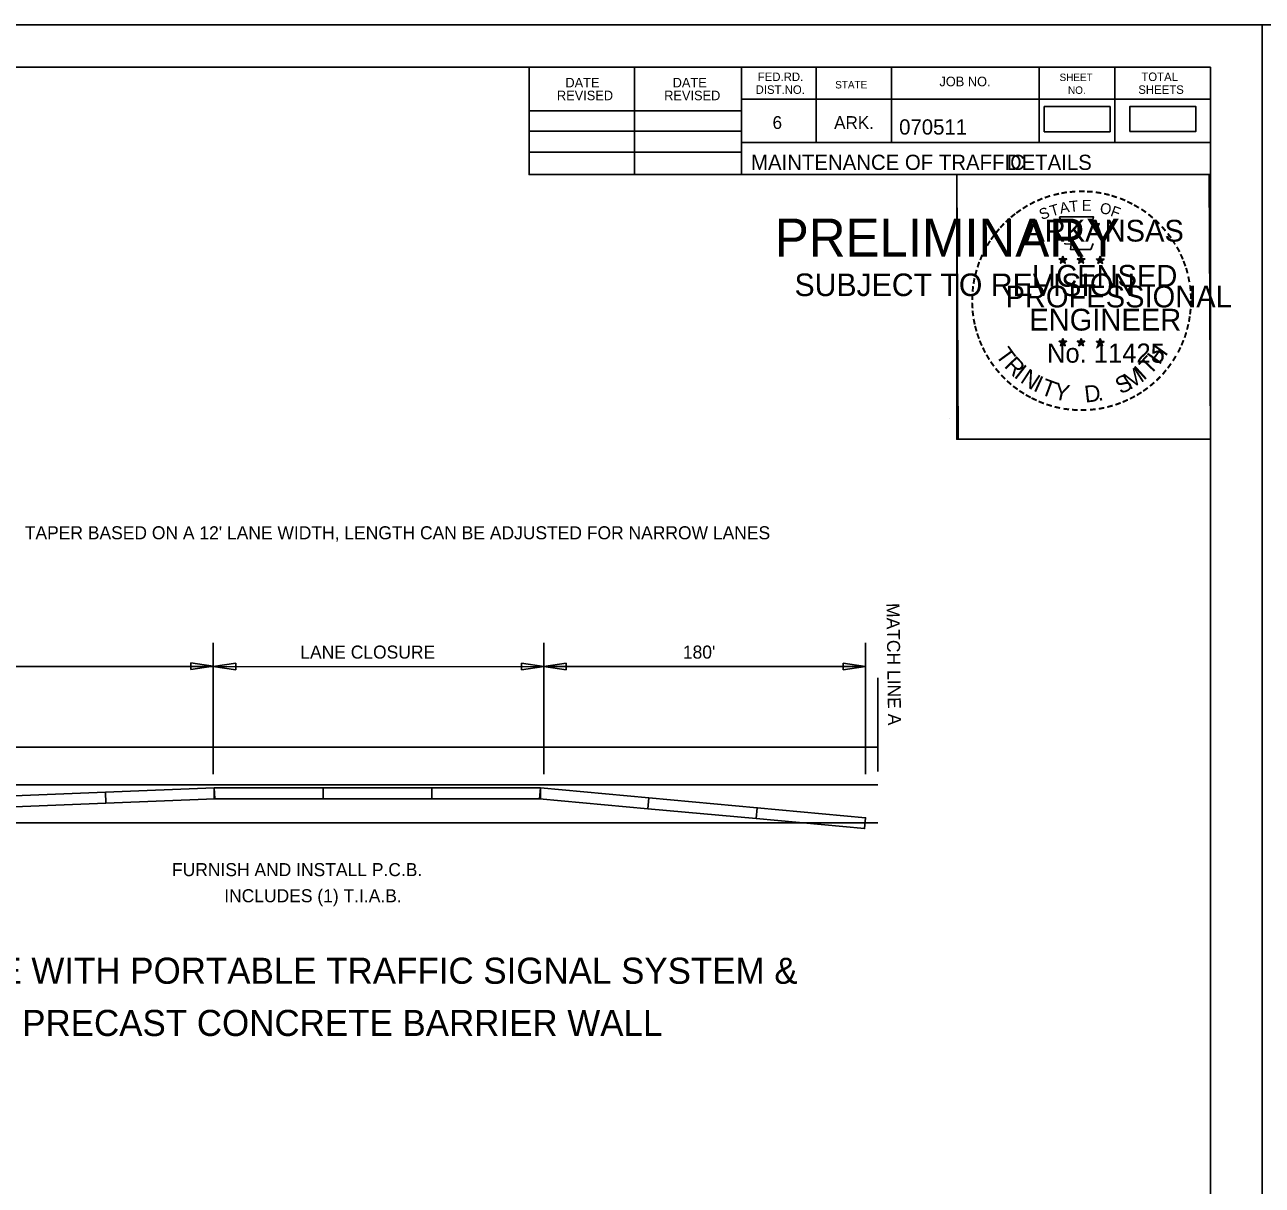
# Model space of a CAD drawing. Extents: x 1398460 to 1408037, y 380768 to 383968.
# Drawn here: x 1400097 to 1400666, y 382368 to 382901 of the extents above; entities that cross this region are included whole.
import ezdxf

# ---------------------------------------------------------------- set-up
doc = ezdxf.new("R2010")
doc.units = 0
for name, color, linetype in [('Default', 7, 'Continuous'), ('R_Border', 7, 'Continuous'), ('R_Border PE', 7, 'Continuous'), ('R_Border Prem', 7, 'Continuous'), ('R_Dimension', 7, 'Continuous'), ('R_No Plot', 7, 'Continuous'), ('T_Vehicle Path Rt', 7, 'Continuous')]:
    doc.layers.add(name, color=color, linetype=linetype)

msp = doc.modelspace()

# ---------------------------------------------------------------- linework, layer by layer
at = {"layer": 'Default'}
for p, q in [((1400183.41, 382616.76), (1400183.41, 382556.41)), ((1400335.34, 382616.76), (1400335.34, 382556.41)), ((1400483.24, 382616.76), (1400483.24, 382556.41)), ((1400173.1, 382604.56), (1400173.1, 382607.65)), ((1400173.1, 382607.65), (1400183.41, 382606.11)), ((1400183.41, 382605.97), (1400193.71, 382607.52)), ((1400193.71, 382607.52), (1400193.71, 382604.43)), ((1400325.04, 382604.43), (1400325.04, 382607.52)), ((1400325.04, 382607.52), (1400335.34, 382605.97)), ((1400335.34, 382605.97), (1400345.65, 382607.52)), ((1400345.65, 382607.52), (1400345.65, 382604.43)), ((1400472.93, 382604.43), (1400472.93, 382607.52)), ((1400472.93, 382607.52), (1400483.24, 382605.97)), ((1400183.41, 382605.97), (1399933.68, 382605.97)), ((1400183.41, 382606.11), (1400173.1, 382604.56)), ((1400193.71, 382604.43), (1400183.41, 382605.97)), ((1400335.34, 382605.84), (1400183.41, 382605.97)), ((1400335.34, 382605.97), (1400325.04, 382604.43)), ((1400335.34, 382605.97), (1400483.24, 382605.97)), ((1400345.65, 382604.43), (1400335.34, 382605.97)), ((1400483.24, 382605.97), (1400472.93, 382604.43)), ((1400488.87, 382600.78), (1400488.87, 382557.73)), ((1399825.51, 382568.89), (1400488.87, 382568.89)), ((1399825.51, 382551.51), (1400488.87, 382551.51)), ((1399825.51, 382534.12), (1400488.87, 382534.12))]:
    msp.add_line(p, q, dxfattribs=at)
at = {"layer": 'R_Border'}
for p, q in [((1399060.87, 382881.42), (1400641.77, 382881.42)), ((1400328.57, 382832.02), (1400328.57, 382881.42)), ((1400376.97, 382832.02), (1400376.97, 382881.42)), ((1400426.27, 382881.42), (1400426.27, 382832.02)), ((1400460.47, 382881.42), (1400460.47, 382846.72)), ((1400495.17, 382881.42), (1400495.17, 382846.72)), ((1400563.07, 382881.42), (1400563.07, 382846.72)), ((1400597.77, 382881.42), (1400597.77, 382846.72)), ((1400641.77, 381854.12), (1400641.77, 382881.42)), ((1400641.77, 382866.72), (1400426.27, 382866.72)), ((1400641.77, 382866.82), (1400641.77, 382866.82)), ((1400328.57, 382861.32), (1400426.27, 382861.32)), ((1400328.57, 382852.02), (1400426.27, 382852.02)), ((1400641.77, 382846.72), (1400426.27, 382846.72)), ((1400441.07, 382846.72), (1400641.77, 382846.72)), ((1400328.57, 382842.32), (1400426.27, 382842.32)), ((1400641.77, 382832.02), (1400328.57, 382832.02))]:
    msp.add_line(p, q, dxfattribs=at)
at = {"layer": 'R_Border PE'}
for p, q in [((1400573.94, 382794.56), (1400573.73, 382793.3)), ((1400573.94, 382792.74), (1400573.94, 382794.56)), ((1400573.94, 382794.56), (1400574.18, 382793.31)), ((1400582.29, 382794.56), (1400582.08, 382793.3)), ((1400582.29, 382792.74), (1400582.29, 382794.56)), ((1400582.29, 382794.56), (1400582.53, 382793.31)), ((1400572.19, 382793.29), (1400573.94, 382792.74)), ((1400572.19, 382793.29), (1400573.46, 382793.07)), ((1400572.19, 382793.29), (1400573.38, 382792.68)), ((1400572.86, 382791.25), (1400573.94, 382792.74)), ((1400572.86, 382791.25), (1400573.49, 382792.47)), ((1400572.86, 382791.25), (1400573.93, 382792.34)), ((1400575, 382791.25), (1400573.93, 382792.32)), ((1400575.67, 382793.29), (1400573.94, 382792.74)), ((1400575, 382791.25), (1400573.94, 382792.74)), ((1400575.67, 382793.29), (1400574.24, 382793.05)), ((1400575, 382791.25), (1400574.32, 382792.71)), ((1400575.67, 382793.29), (1400574.65, 382792.78)), ((1400580.54, 382793.29), (1400582.29, 382792.74)), ((1400580.54, 382793.29), (1400581.81, 382793.07)), ((1400580.54, 382793.29), (1400581.73, 382792.68)), ((1400581.21, 382791.25), (1400582.29, 382792.74)), ((1400581.21, 382791.25), (1400581.84, 382792.47)), ((1400581.21, 382791.25), (1400582.28, 382792.34)), ((1400583.35, 382791.25), (1400582.28, 382792.32)), ((1400584.02, 382793.29), (1400582.29, 382792.74)), ((1400583.35, 382791.25), (1400582.29, 382792.74)), ((1400584.02, 382793.29), (1400582.59, 382793.05)), ((1400583.35, 382791.25), (1400582.67, 382792.71)), ((1400584.02, 382793.29), (1400583, 382792.78)), ((1400589.36, 382793.23), (1400591.11, 382792.68)), ((1400589.36, 382793.23), (1400590.63, 382793.01)), ((1400589.36, 382793.23), (1400590.55, 382792.62)), ((1400590.03, 382791.19), (1400591.11, 382792.68)), ((1400590.03, 382791.19), (1400590.66, 382792.41)), ((1400590.03, 382791.19), (1400591.1, 382792.28)), ((1400591.11, 382794.5), (1400590.9, 382793.24)), ((1400592.17, 382791.19), (1400591.1, 382792.26)), ((1400591.11, 382792.68), (1400591.11, 382794.5)), ((1400591.11, 382794.5), (1400591.35, 382793.25)), ((1400592.84, 382793.23), (1400591.11, 382792.68)), ((1400592.17, 382791.19), (1400591.11, 382792.68)), ((1400592.84, 382793.23), (1400591.41, 382792.99)), ((1400592.17, 382791.19), (1400591.49, 382792.65)), ((1400592.84, 382793.23), (1400591.82, 382792.72)), ((1400572.17, 382755.43), (1400573.92, 382754.87)), ((1400572.17, 382755.43), (1400573.44, 382755.2)), ((1400572.17, 382755.43), (1400573.36, 382754.82)), ((1400572.84, 382753.39), (1400573.92, 382754.87)), ((1400573.92, 382756.7), (1400573.71, 382755.44)), ((1400573.92, 382754.87), (1400573.92, 382756.7)), ((1400573.92, 382756.7), (1400574.16, 382755.45)), ((1400575.65, 382755.43), (1400573.92, 382754.87)), ((1400574.98, 382753.39), (1400573.92, 382754.87)), ((1400575.65, 382755.43), (1400574.22, 382755.18)), ((1400574.98, 382753.39), (1400574.3, 382754.84)), ((1400575.65, 382755.43), (1400574.63, 382754.92)), ((1400580.52, 382755.43), (1400582.26, 382754.87)), ((1400580.52, 382755.43), (1400581.78, 382755.2)), ((1400580.52, 382755.43), (1400581.7, 382754.82)), ((1400581.18, 382753.39), (1400582.26, 382754.87)), ((1400582.26, 382756.7), (1400582.06, 382755.44)), ((1400582.26, 382754.87), (1400582.26, 382756.7)), ((1400582.26, 382756.7), (1400582.51, 382755.45)), ((1400584, 382755.43), (1400582.26, 382754.87)), ((1400583.33, 382753.39), (1400582.26, 382754.87)), ((1400584, 382755.43), (1400582.57, 382755.18)), ((1400583.33, 382753.39), (1400582.64, 382754.84)), ((1400584, 382755.43), (1400582.98, 382754.92)), ((1400589.35, 382755.38), (1400591.1, 382754.82)), ((1400589.35, 382755.38), (1400590.62, 382755.15)), ((1400589.35, 382755.38), (1400590.54, 382754.77)), ((1400590.02, 382753.34), (1400591.1, 382754.82)), ((1400591.1, 382756.65), (1400590.89, 382755.39)), ((1400591.1, 382754.82), (1400591.1, 382756.65)), ((1400591.1, 382756.65), (1400591.34, 382755.4)), ((1400592.83, 382755.38), (1400591.1, 382754.82)), ((1400592.16, 382753.34), (1400591.1, 382754.82)), ((1400592.83, 382755.38), (1400591.4, 382755.13)), ((1400592.16, 382753.34), (1400591.48, 382754.79)), ((1400592.83, 382755.38), (1400591.81, 382754.87)), ((1400572.84, 382753.39), (1400573.47, 382754.61)), ((1400572.84, 382753.39), (1400573.91, 382754.47)), ((1400574.98, 382753.39), (1400573.91, 382754.46)), ((1400581.18, 382753.39), (1400581.81, 382754.61)), ((1400581.18, 382753.39), (1400582.25, 382754.47)), ((1400583.33, 382753.39), (1400582.25, 382754.46)), ((1400590.02, 382753.34), (1400590.65, 382754.56)), ((1400590.02, 382753.34), (1400591.09, 382754.42)), ((1400592.16, 382753.34), (1400591.09, 382754.41))]:
    msp.add_line(p, q, dxfattribs=at)
for points in [[(1400572.4, 382812.68), (1400573.74, 382808.55)], [(1400589.95, 382808.07), (1400590.66, 382809.49), (1400587.24, 382809.37), (1400587.98, 382812.68), (1400572.4, 382812.68)], [(1400574.86, 382800.57), (1400574.86, 382800.13), (1400577.67, 382800.04), (1400577.4, 382797.67), (1400586.75, 382797.67), (1400587.76, 382800.35)], [(1400573.94, 382794.56), (1400575, 382791.25), (1400572.19, 382793.29), (1400575.67, 382793.29), (1400572.86, 382791.25), (1400573.94, 382794.56)], [(1400582.29, 382794.56), (1400583.35, 382791.25), (1400580.54, 382793.29), (1400584.02, 382793.29), (1400581.21, 382791.25), (1400582.29, 382794.56)], [(1400591.11, 382794.5), (1400592.17, 382791.19), (1400589.36, 382793.23), (1400592.84, 382793.23), (1400590.03, 382791.19), (1400591.11, 382794.5)], [(1400573.92, 382756.7), (1400574.98, 382753.39), (1400572.17, 382755.43), (1400575.65, 382755.43), (1400572.84, 382753.39), (1400573.92, 382756.7)], [(1400582.26, 382756.7), (1400583.33, 382753.39), (1400580.52, 382755.43), (1400584, 382755.43), (1400581.18, 382753.39), (1400582.26, 382756.7)], [(1400591.1, 382756.65), (1400592.16, 382753.34), (1400589.35, 382755.38), (1400592.83, 382755.38), (1400590.02, 382753.34), (1400591.1, 382756.65)]]:
    msp.add_lwpolyline(points, dxfattribs=at)
for centre, radius in [((1400573.93, 382792.73), 0.861), ((1400573.93, 382792.73), 0.723), ((1400573.93, 382792.73), 0.579), ((1400573.93, 382792.73), 0.495), ((1400573.93, 382792.73), 0.374), ((1400573.93, 382792.73), 0.248), ((1400573.93, 382792.73), 0.148), ((1400582.28, 382792.73), 0.861), ((1400582.28, 382792.73), 0.723), ((1400582.28, 382792.73), 0.579), ((1400582.28, 382792.73), 0.495), ((1400582.28, 382792.73), 0.374), ((1400582.28, 382792.73), 0.248), ((1400582.28, 382792.73), 0.148), ((1400591.1, 382792.67), 0.861), ((1400591.1, 382792.67), 0.723), ((1400591.1, 382792.67), 0.579), ((1400591.1, 382792.67), 0.495), ((1400591.1, 382792.67), 0.374), ((1400591.1, 382792.67), 0.248), ((1400591.1, 382792.67), 0.148), ((1400573.91, 382754.87), 0.861), ((1400573.91, 382754.87), 0.723), ((1400573.91, 382754.87), 0.579), ((1400573.91, 382754.87), 0.495), ((1400573.91, 382754.87), 0.374), ((1400573.91, 382754.87), 0.248), ((1400573.91, 382754.87), 0.148), ((1400582.26, 382754.87), 0.861), ((1400582.26, 382754.87), 0.723), ((1400582.26, 382754.87), 0.579), ((1400582.26, 382754.87), 0.495), ((1400582.26, 382754.87), 0.374), ((1400582.26, 382754.87), 0.248), ((1400582.26, 382754.87), 0.148), ((1400591.09, 382754.82), 0.861), ((1400591.09, 382754.82), 0.723), ((1400591.09, 382754.82), 0.579), ((1400591.09, 382754.82), 0.495), ((1400591.09, 382754.82), 0.374), ((1400591.09, 382754.82), 0.248), ((1400591.09, 382754.82), 0.148)]:
    msp.add_circle(centre, radius, dxfattribs=at)
at = {"layer": 'R_Dimension'}
for points in [[(1400565.37, 382851.73), (1400595.64, 382851.73), (1400595.64, 382863.28), (1400565.37, 382863.28)], [(1400604.7, 382851.79), (1400634.97, 382851.79), (1400634.97, 382863.35), (1400604.7, 382863.35)]]:
    msp.add_lwpolyline(points, close=True, dxfattribs=at)
at = {"layer": 'R_No Plot'}
for p, q in [((1398998.86, 382900.89), (1400665.53, 382900.89)), ((1400521.94, 382719.74), (1400521.94, 382719.74))]:
    msp.add_line(p, q, dxfattribs=at)
for points in [[(1398998.83, 382900.89), (1400665.53, 382900.89), (1400665.53, 381834.2), (1398998.83, 381834.2)], [(1400665.53, 382900.89), (1402332.23, 382900.89), (1402332.23, 381834.2), (1400665.53, 381834.2)], [(1400230.47, 382881.42), (1400328.57, 382881.42), (1400328.57, 382832.02), (1400409.13, 382832.02), (1400525.12, 382832.02), (1400525.12, 382710.36), (1400641.77, 382710.36), (1400641.77, 381854.12), (1399060.87, 381854.12), (1399060.87, 382881.42)], [(1400525.12, 382832.02), (1400641.16, 382832.02), (1400641.77, 382710.36), (1400525.73, 382710.36)]]:
    msp.add_lwpolyline(points, close=True, dxfattribs=at)
at = {"layer": 'T_Vehicle Path Rt'}
for points in [[(1400133.9, 382548.17), (1400183.86, 382550.14), (1400184.06, 382545.15), (1400134.1, 382543.17)], [(1400183.86, 382550.14), (1400233.86, 382550.14), (1400233.86, 382545.14), (1400183.86, 382545.14)], [(1400233.86, 382550.14), (1400283.86, 382550.14), (1400283.86, 382545.14), (1400233.86, 382545.14)], [(1400283.86, 382550.14), (1400333.86, 382550.14), (1400333.86, 382545.14), (1400283.86, 382545.14)], [(1400333.86, 382550.14), (1400383.65, 382545.58), (1400383.2, 382540.6), (1400333.41, 382545.16)], [(1400083.94, 382546.2), (1400133.9, 382548.17), (1400134.1, 382543.17), (1400084.14, 382541.2)], [(1400383.65, 382545.58), (1400433.45, 382541.02), (1400432.99, 382536.04), (1400383.2, 382540.6)], [(1400433.45, 382541.02), (1400483.24, 382536.45), (1400482.78, 382531.48), (1400432.99, 382536.04)]]:
    msp.add_lwpolyline(points, close=True, dxfattribs=at)

# ---------------------------------------------------------------- texts
at = {"layer": 'Default'}
msp.add_text('MATCH LINE A', height=6, rotation=270.8059, dxfattribs=at).set_placement((1400492.8, 382635.07))
for s, height, p in [('LANE CLOSURE', 6, (1400223.42, 382609.58)), ("180'", 6, (1400399.25, 382609.58)), ('FURNISH AND INSTALL P.C.B. ', 6, (1400164.45, 382509.6)), ('INCLUDES (1) T.I.A.B.', 6, (1400188.45, 382497.6)), ('LANE CLOSURE WITH PORTABLE TRAFFIC SIGNAL SYSTEM &', 12, (1399971.4, 382460.14)), ('PRECAST CONCRETE BARRIER WALL', 12, (1400095.6, 382436.14))]:
    msp.add_text(s, height=height, dxfattribs=at).set_placement(p)
at = {"layer": 'R_Border'}
for s, height, p in [('DATE', 4.396, (1400345.26, 382872.1)), ('DATE', 4.396, (1400394.56, 382872.1)), ('FED.RD.', 3.91, (1400433.67, 382875.02)), ('STATE', 3.42, (1400469.27, 382871.62)), ('JOB NO.', 4.396, (1400517.17, 382872.62)), ('SHEET', 3.42, (1400572.37, 382875.02)), ('TOTAL', 3.91, (1400609.97, 382875.02)), ('REVISED', 4.396, (1400341.36, 382866.2)), ('REVISED', 4.396, (1400390.66, 382866.2)), ('DIST.NO.', 3.91, (1400432.67, 382869.12)), ('NO.', 3.42, (1400576.27, 382869.12)), ('SHEETS', 3.91, (1400608.57, 382869.12)), ('6', 5.86, (1400440.47, 382853.02)), ('ARK.', 5.861, (1400468.77, 382853.02)), ('070511', 7, (1400498.65, 382850.42)), ('MAINTENANCE OF TRAFFIC', 7, (1400430.58, 382834.17)), (' DETAILS', 7, (1400545.58, 382834.17))]:
    msp.add_text(s, height=height, dxfattribs=at).set_placement(p)
at = {"layer": 'R_Border PE'}
for s, height, rotation, p in [('-', 8, 13.6302, (1400569.89, 382819.52)), ('-', 8, 10.2193, (1400573.28, 382820.33)), ('-', 8, 5.8968, (1400576.92, 382820.88)), ('-', 8, 0.1862, (1400580.78, 382821.24)), ('-', 8, 357.743, (1400584.4, 382821.18)), ('-', 8, 352.1617, (1400588.12, 382820.9)), ('-', 8, 347.2049, (1400591.71, 382820.33)), ('-', 8, 34.0636, (1400556.82, 382813.54)), ('-', 8, 28.7918, (1400559.8, 382815.39)), ('-', 8, 24.3072, (1400562.97, 382816.97)), ('-', 8, 19.1761, (1400566.14, 382818.32)), ('T', 5, 16.4036, (1400568.74, 382812.73)), ('A', 5, 11.2132, (1400572.87, 382813.98)), ('T', 5, 6.0228, (1400577.12, 382814.81)), ('E', 5, 0.8323, (1400582.64, 382815.36)), ('O', 5, 350.4515, (1400590.66, 382814.31)), ('F', 5, 340.0707, (1400595.43, 382813.17)), ('-', 8, 342.3362, (1400594.89, 382819.55)), ('-', 8, 337.8551, (1400598.56, 382818.44)), ('-', 8, 334.1211, (1400601.72, 382817.08)), ('-', 8, 329.6409, (1400604.61, 382815.67)), ('-', 8, 42.9622, (1400549.38, 382807.59)), ('-', 8, 38.9507, (1400551.55, 382809.67)), ('-', 8, 36.2317, (1400553.93, 382811.56)), ('S', 5, 21.594, (1400564.17, 382811.07)), ('-', 8, 325.8627, (1400607.83, 382813.86)), ('-', 8, 320.5297, (1400610.88, 382811.73)), ('-', 8, 50.6142, (1400545.13, 382802.77)), ('-', 8, 48.4231, (1400547.14, 382805.2)), ('-', 8, 315.5786, (1400613.87, 382809.29)), ('-', 8, 309.8797, (1400616.72, 382806.54)), ('-', 8, 58.0706, (1400541.44, 382797.3)), ('-', 8, 54.2325, (1400543.06, 382799.93)), ('-', 8, 306.6522, (1400619.34, 382803.53)), ('-', 7, 303.6753, (1400621.77, 382800.69)), ('-', 8, 67.7743, (1400538.58, 382791.17)), ('-', 8, 62.8713, (1400539.87, 382794.23)), ('-', 8, 299.6684, (1400623.37, 382797.66)), ('-', 8, 294.6628, (1400624.99, 382794.6)), ('-', 8, 72.3945, (1400537.48, 382788.02)), ('-', 8, 290.5728, (1400626.27, 382791.71)), ('-', 8, 285.1233, (1400627.44, 382788.81)), ('-', 8, 81.2013, (1400535.84, 382780.89)), ('-', 8, 75.461, (1400536.5, 382784.45)), ('-', 8, 280.5493, (1400628.44, 382785.1)), ('-', 8, 85.1863, (1400535.46, 382777.43)), ('-', 8, 276.5962, (1400629.25, 382781.26)), ('-', 8, 94.1959, (1400535.51, 382770.3)), ('-', 8, 89.0622, (1400535.33, 382773.93)), ('-', 8, 274.3301, (1400629.55, 382777.65)), ('-', 8, 269.9407, (1400629.72, 382774.49)), ('-', 8, 98.9479, (1400535.87, 382766.97)), ('-', 8, 260.9953, (1400629.27, 382767.89)), ('-', 8, 263.5172, (1400629.63, 382771.16)), ('-', 8, 101.7149, (1400536.54, 382763.3)), ('-', 8, 105.4578, (1400537.35, 382760.33)), ('-', 8, 255.7626, (1400628.72, 382764.5)), ('-', 8, 109.0874, (1400538.43, 382757.17)), ('-', 8, 114.0643, (1400539.7, 382754.19)), ('-', 8, 247.8887, (1400626.7, 382757.54)), ('-', 8, 252.8681, (1400627.82, 382760.9)), ('-', 8, 115.7289, (1400541.22, 382751.1)), ('-', 8, 120.4471, (1400543.01, 382748.17)), ('T', 7.7, 306.0406, (1400542.71, 382749.06)), ('T', 7.7, 46.6444, (1400613.87, 382739.53)), ('H', 7.7, 54.6088, (1400618.31, 382744.24)), ('-', 8, 244.6197, (1400625.39, 382754.39)), ('-', 8, 125.8934, (1400545.02, 382745.37)), ('R', 7.7, 314.005, (1400546.53, 382743.83)), ('I', 7.7, 321.9694, (1400551.03, 382739.17)), ('M', 7.7, 32.6563, (1400604.64, 382732.9)), ('I', 7.7, 42.1136, (1400611.06, 382737.14)), ('-', 8, 233.8452, (1400621.41, 382747.37)), ('-', 8, 239.0712, (1400623.42, 382750.63)), ('-', 8, 130.7181, (1400547.33, 382742.61)), ('-', 8, 134.2238, (1400549.92, 382739.88)), ('N', 7.7, 326.5002, (1400553.86, 382736.81)), ('I', 7.7, 335.3603, (1400559.91, 382732.88)), ('T', 7.7, 339.8912, (1400563.21, 382731.24)), ('S', 7.7, 26.9312, (1400600.44, 382730.87)), ('-', 8, 225.7653, (1400616.87, 382741.72)), ('-', 8, 231.2538, (1400619.26, 382744.54)), ('-', 8, 138.9338, (1400552.54, 382737.56)), ('-', 8, 144.6463, (1400555.32, 382735.53)), ('-', 8, 148.0898, (1400558.13, 382733.68)), ('Y', 7.7, 347.8556, (1400569.3, 382729.01)), ('D', 7.7, 6.3969, (1400584.22, 382727.22)), ('-', 8, 212.2491, (1400608.84, 382734.88)), ('-', 8, 215.7363, (1400611.51, 382736.81)), ('-', 8, 221.0851, (1400614.26, 382739.17)), ('-', 8, 151.5704, (1400561.02, 382732.05)), ('-', 8, 154.6002, (1400563.63, 382730.82)), ('-', 8, 158.5612, (1400566.75, 382729.55)), ('-', 8, 162.7983, (1400570.19, 382728.48)), ('.', 7.7, 13.7642, (1400590.18, 382727.86)), ('-', 8, 195.4743, (1400596.45, 382728.98)), ('-', 8, 200.7184, (1400599.84, 382730.19)), ('-', 8, 204.2516, (1400602.93, 382731.55)), ('-', 8, 207.3568, (1400606.05, 382733.15)), ('-', 8, 167.5555, (1400573.76, 382727.66)), ('-', 8, 173.1155, (1400577.62, 382727.11)), ('-', 8, 176.5183, (1400581.36, 382726.85)), ('-', 8, 181.5918, (1400585.08, 382726.94)), ('-', 8, 185.8167, (1400589.13, 382727.32)), ('-', 8, 191.2858, (1400592.81, 382727.98))]:
    msp.add_text(s, height=height, rotation=rotation, dxfattribs=at).set_placement(p)
for s, height, p in [('ARKANSAS', 10, (1400556.66, 382801.24)), ('LICENSED', 10, (1400559.65, 382780.5)), ('DWB', 0.05, (1400573.87, 382792.71)), ('DWB', 0.05, (1400582.22, 382792.71)), ('DWB', 0.05, (1400591.04, 382792.66)), ('PROFESSIONAL', 10, (1400547.53, 382770.98)), ('ENGINEER', 10, (1400558.47, 382760.35)), ('DWB', 0.05, (1400573.85, 382754.85)), ('DWB', 0.05, (1400582.2, 382754.85)), ('DWB', 0.05, (1400591.03, 382754.8)), ('No. 11425', 8.785, (1400566.6, 382745.6))]:
    msp.add_text(s, height=height, dxfattribs=at).set_placement(p)
at = {"layer": 'R_Border Prem'}
for s, height, p in [('PRELIMINARY', 17.5, (1400441.52, 382794.33)), ('DWB', 0.05, (1400445.26, 382803.58)), ('SUBJECT TO REVISION', 10.3756, (1400450.57, 382776.19))]:
    msp.add_text(s, height=height, dxfattribs=at).set_placement(p)
at = {"layer": 'R_No Plot'}
msp.add_text("TAPER BASED ON A 12' LANE WIDTH, LENGTH CAN BE ADJUSTED FOR NARROW LANES", height=6, dxfattribs=at).set_placement((1400096.78, 382664.41))

doc.saveas('drawing.dxf')
